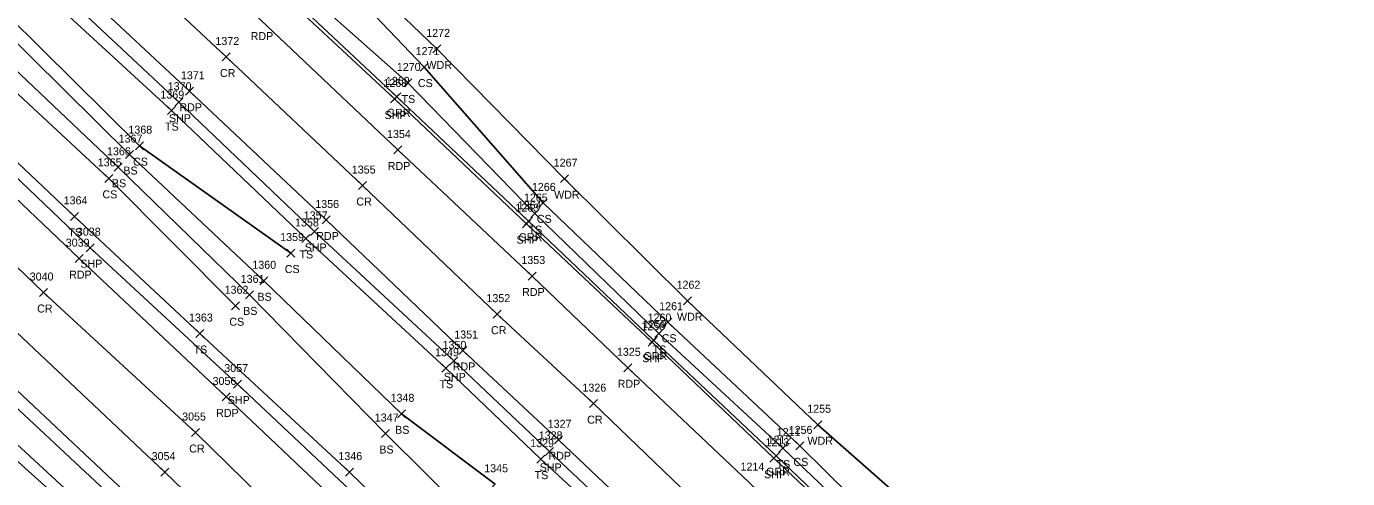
# Model space of a CAD drawing. Extents: x 1647574 to 1652703, y 212895 to 228670.
# Drawn here: x 1649589.7 to 1649920, y 226490.7 to 226603.8 of the extents above; entities that cross this region are included whole.
import ezdxf

# ---------------------------------------------------------------- set-up
doc = ezdxf.new("R2010")
doc.units = 0
for name, color, linetype in [('L_A', 7, 'Continuous'), ('L_I', 7, 'Continuous'), ('L_TIC', 7, 'Continuous'), ('LAWA', 7, 'Continuous'), ('LELB', 7, 'Continuous'), ('P_A', 7, 'Continuous'), ('P_I', 7, 'Continuous'), ('P_TIC', 7, 'Continuous'), ('PET', 7, 'Continuous'), ('PRC', 7, 'Continuous'), ('PSP', 7, 'Continuous'), ('R_A', 7, 'Continuous'), ('R_I', 7, 'Continuous'), ('R_TIC', 7, 'Continuous'), ('RGR', 7, 'Continuous')]:
    doc.layers.add(name, color=color, linetype=linetype)

msp = doc.modelspace()

# ---------------------------------------------------------------- linework, layer by layer
at = {"layer": 'L_TIC'}
for points in [[(1649691.31, 226597.17), (1649693.31, 226599.17)], [(1649693.31, 226597.17), (1649691.31, 226599.17)], [(1649688.09, 226592.62), (1649690.09, 226594.62)], [(1649690.09, 226592.62), (1649688.09, 226594.62)], [(1649684.05, 226588.65), (1649686.05, 226590.65)], [(1649686.05, 226588.65), (1649684.05, 226590.65)], [(1649624.91, 226581.74), (1649626.91, 226583.74)], [(1649626.91, 226581.74), (1649624.91, 226583.74)], [(1649614.46, 226570.75), (1649616.46, 226572.75)], [(1649616.46, 226570.75), (1649614.46, 226572.75)], [(1649616.9, 226572.97), (1649618.9, 226574.97)], [(1649618.9, 226572.97), (1649616.9, 226574.97)], [(1649611.61, 226567.57), (1649613.61, 226569.57)], [(1649613.61, 226567.57), (1649611.61, 226569.57)], [(1649609.24, 226564.8), (1649611.24, 226566.8)], [(1649611.24, 226564.8), (1649609.24, 226566.8)], [(1649723.22, 226564.72), (1649725.22, 226566.72)], [(1649725.22, 226564.72), (1649723.22, 226566.72)], [(1649717.83, 226558.66), (1649719.83, 226560.66)], [(1649719.83, 226558.66), (1649717.83, 226560.66)], [(1649600.72, 226555.3), (1649602.72, 226557.3)], [(1649602.72, 226555.3), (1649600.72, 226557.3)], [(1649715.78, 226555.99), (1649717.78, 226557.99)], [(1649717.78, 226555.99), (1649715.78, 226557.99)], [(1649658.53, 226549.77), (1649660.53, 226551.77)], [(1649660.53, 226549.77), (1649658.53, 226551.77)], [(1649654.81, 226546.12), (1649656.81, 226548.12)], [(1649656.81, 226546.12), (1649654.81, 226548.12)], [(1649647.98, 226539.18), (1649649.98, 226541.18)], [(1649649.98, 226539.18), (1649647.98, 226541.18)], [(1649644.41, 226535.66), (1649646.41, 226537.66)], [(1649646.41, 226535.66), (1649644.41, 226537.66)], [(1649753.94, 226534.2), (1649755.94, 226536.2)], [(1649755.94, 226534.2), (1649753.94, 226536.2)], [(1649640.96, 226532.94), (1649642.96, 226534.94)], [(1649642.96, 226532.94), (1649640.96, 226534.94)], [(1649749.04, 226528.83), (1649751.04, 226530.83)], [(1649751.04, 226528.83), (1649749.04, 226530.83)], [(1649632.05, 226525.99), (1649634.05, 226527.99)], [(1649634.05, 226525.99), (1649632.05, 226527.99)], [(1649746.79, 226525.99), (1649748.79, 226527.99)], [(1649748.79, 226525.99), (1649746.79, 226527.99)], [(1649693.54, 226517.32), (1649695.54, 226519.32)], [(1649695.54, 226517.32), (1649693.54, 226519.32)], [(1649682.4, 226505.92), (1649684.4, 226507.92)], [(1649684.4, 226505.92), (1649682.4, 226507.92)], [(1649678.45, 226500.99), (1649680.45, 226502.99)], [(1649680.45, 226500.99), (1649678.45, 226502.99)], [(1649786.56, 226503.18), (1649788.56, 226505.18)], [(1649788.56, 226503.18), (1649786.56, 226505.18)], [(1649781.98, 226497.9), (1649783.98, 226499.9)], [(1649783.98, 226497.9), (1649781.98, 226499.9)], [(1649717.31, 226494.58), (1649719.31, 226496.58)], [(1649719.31, 226494.58), (1649717.31, 226496.58)], [(1649777.8, 226497.35), (1649779.8, 226499.35)], [(1649779.8, 226497.35), (1649777.8, 226499.35)], [(1649669.41, 226491.35), (1649671.41, 226493.35)], [(1649671.41, 226491.35), (1649669.41, 226493.35)]]:
    msp.add_lwpolyline(points, dxfattribs=at)
at = {"layer": 'LAWA'}
msp.add_lwpolyline([(1650224.82, 226043.26), (1650200.57, 226071.14), (1650179.14, 226096.39), (1650156.93, 226122.13), (1650126.46, 226158.5), (1650102.32, 226186.03), (1650070.86, 226221.7), (1650047.25, 226248.26), (1650033.72, 226259.55), (1650015.55, 226280.28), (1649981.36, 226313.37), (1649950.59, 226346.36), (1649922.81, 226373.8), (1649891.44, 226407.34), (1649856.77, 226439.08), (1649829.63, 226467.03), (1649787.56, 226504.18), (1649754.94, 226535.2), (1649724.22, 226565.72), (1649692.31, 226598.17), (1649653.67, 226635.29), (1649620.52, 226666.86), (1649581.67, 226703.66)], dxfattribs=at)
at = {"layer": 'LELB'}
for points in [[(1649699.67, 226481.91), (1649679.45, 226501.99), (1649645.41, 226536.66), (1649612.61, 226568.57), (1649578.32, 226600.99), (1649543.98, 226632.95), (1649509.04, 226666.44), (1649473.07, 226698.81), (1649440.27, 226731.3), (1649435.72, 226737.04), (1649408.87, 226762.28), (1649371.65, 226797.42), (1649335.46, 226831.54), (1649323.17, 226842.84), (1649315.96, 226850.35), (1649312.9, 226852.88), (1649303.05, 226862.63), (1649272.9, 226885.04), (1649244.53, 226913.23), (1649219.14, 226937.73), (1649217.77, 226942.22), (1649215.75, 226944.46), (1649217.78, 226946.35), (1649219.53, 226943.85)], [(1650010.63, 226272.18), (1649976.36, 226308.87), (1649944.85, 226340.83), (1649916.6, 226368.96), (1649885.58, 226401.45), (1649851.41, 226433.71), (1649822.12, 226460.28), (1649782.98, 226498.9), (1649750.04, 226529.83), (1649718.83, 226559.66), (1649689.09, 226593.62), (1649652.01, 226632.5), (1649616.85, 226664.27), (1649578.69, 226701.52), (1649544.7, 226732.63), (1649511.82, 226765.51), (1649477.06, 226797.14), (1649442.21, 226831.27), (1649405.15, 226865.62), (1649378.95, 226891.41), (1649346.59, 226917.07), (1649311.19, 226946.22)], [(1649699.67, 226481.91), (1649706.82, 226489.3), (1649683.4, 226506.92), (1649648.98, 226540.18), (1649615.46, 226571.75), (1649582.54, 226604.31), (1649545.88, 226635.11), (1649514.99, 226670.75), (1649476.91, 226703.47), (1649443.87, 226735.13), (1649437.39, 226738.45), (1649410.25, 226763.49), (1649372.93, 226798.59), (1649336.35, 226832.76), (1649324.5, 226844.21), (1649317.41, 226851.47), (1649314.57, 226854.84), (1649305.82, 226864.42), (1649279.73, 226892.76), (1649248.17, 226918.18), (1649224.51, 226943.02), (1649219.53, 226943.85)], [(1650213.15, 226037.1), (1650185.87, 226070.33), (1650156.97, 226103.72), (1650126.82, 226139.03), (1650097.45, 226172.49), (1650065.12, 226208.19), (1650039.15, 226236.7), (1650005.62, 226272.51), (1649977.06, 226302.34), (1649946.85, 226333.69), (1649915.81, 226365.02), (1649884.88, 226395.87), (1649852.74, 226426.8), (1649817.4, 226461.44), (1649778.8, 226498.35), (1649747.79, 226526.99), (1649716.78, 226556.99), (1649685.05, 226589.65), (1649647.22, 226623.29), (1649611.68, 226660.43), (1649573.8, 226694.76)], [(1649655.81, 226547.12), (1649617.9, 226573.97), (1649585.1, 226606.47), (1649550.01, 226639.37), (1649514.99, 226670.75)], [(1649641.96, 226533.94), (1649610.24, 226565.8), (1649574.72, 226598.75), (1649541.82, 226631.16), (1649509.04, 226666.44)], [(1650145.31, 225996.12), (1650155.22, 226000.73), (1650160.97, 226007.39), (1650165.06, 226014.73), (1650162.63, 226023.17), (1650152.14, 226036.38), (1650125.52, 226068.74), (1650101.36, 226098.15), (1650073.79, 226131.47), (1650039.14, 226169.85), (1650006.52, 226208.67), (1649978.85, 226238.77), (1649944.11, 226276), (1649910.77, 226309.61), (1649879.19, 226341.22), (1649849.26, 226371.24), (1649815.2, 226404.44), (1649786.47, 226431.97), (1649749.39, 226466.79), (1649718.31, 226495.58), (1649694.54, 226518.32), (1649659.53, 226550.77), (1649625.91, 226582.74), (1649593.12, 226613.01)], [(1650145.31, 225996.12), (1650126.11, 226017.39), (1650101.66, 226047.08), (1650074.02, 226078.27), (1650048.35, 226107.52), (1650011.02, 226148.89), (1649978.29, 226184.76), (1649948.32, 226216.56), (1649918.31, 226248.62), (1649881.09, 226286.67), (1649854.51, 226315.1), (1649822.53, 226345.57), (1649790.94, 226377.4), (1649759.46, 226406.66), (1649722.98, 226440.72), (1649699.36, 226464.18), (1649670.41, 226492.35), (1649633.05, 226526.99), (1649601.72, 226556.3), (1649565.56, 226590.44)], [(1649576.43, 226518.4), (1649614.41, 226482.98), (1649642.41, 226455.9), (1649685.38, 226415.67), (1649721.92, 226380.74), (1649759.16, 226344.82), (1649794.41, 226310.27), (1649829.09, 226276.12), (1649866.9, 226238.21), (1649900.81, 226202.84), (1649937.1, 226163.93), (1649969.44, 226128.19), (1649998.01, 226097.17), (1650029.45, 226060.68), (1650045.36, 226034.05), (1650069.99, 226009.77), (1650092.51, 225984.63), (1650111.94, 225960.02)], [(1649572.06, 226513.32), (1649610.08, 226478.23), (1649638.08, 226450.58), (1649682.17, 226412.39), (1649718, 226377.59), (1649756, 226340.45), (1649789.26, 226306.39), (1649824.84, 226270.98), (1649865.01, 226237.13), (1649898.41, 226199.96), (1649935.32, 226162.62), (1649968.54, 226127.19), (1649995.98, 226095.51), (1650026.38, 226057.31)], [(1649570.19, 226510.51), (1649608.23, 226476.35), (1649636.57, 226449.06), (1649663.19, 226421.28), (1649670.48, 226414.78), (1649679.22, 226408.18), (1649715.79, 226375.57), (1649754.34, 226338.61), (1649788.1, 226305.21), (1649822.67, 226268.96), (1649860.5, 226231.77), (1649895.97, 226193.57), (1649929.13, 226157.26), (1649962.02, 226120.66), (1649988.9, 226089.08), (1650019.8, 226051.49), (1650041.89, 226022.86), (1650059.37, 225999.62), (1650079.66, 225974.03), (1650096.25, 225946.36)]]:
    msp.add_lwpolyline(points, dxfattribs=at)
at = {"layer": 'P_TIC'}
for points in [[(1649638.62, 226595.15), (1649640.62, 226597.15)], [(1649640.62, 226595.15), (1649638.62, 226597.15)], [(1649626.77, 226583.84), (1649628.77, 226585.84)], [(1649628.77, 226583.84), (1649626.77, 226585.84)], [(1649629.41, 226586.57), (1649631.41, 226588.57)], [(1649631.41, 226586.57), (1649629.41, 226588.57)], [(1649680.67, 226584.65), (1649682.67, 226586.65)], [(1649682.67, 226584.65), (1649680.67, 226586.65)], [(1649681.51, 226571.89), (1649683.51, 226573.89)], [(1649683.51, 226571.89), (1649681.51, 226573.89)], [(1649672.7, 226563), (1649674.7, 226565)], [(1649674.7, 226563), (1649672.7, 226565)], [(1649663.62, 226554.39), (1649665.62, 226556.39)], [(1649665.62, 226554.39), (1649663.62, 226556.39)], [(1649660.7, 226551.53), (1649662.7, 226553.53)], [(1649662.7, 226551.53), (1649660.7, 226553.53)], [(1649713.65, 226553.46), (1649715.65, 226555.46)], [(1649715.65, 226553.46), (1649713.65, 226555.46)], [(1649604.62, 226547.46), (1649606.62, 226549.46)], [(1649606.62, 226547.46), (1649604.62, 226549.46)], [(1649601.84, 226544.72), (1649603.84, 226546.72)], [(1649603.84, 226544.72), (1649601.84, 226546.72)], [(1649715.1, 226540.38), (1649717.1, 226542.38)], [(1649717.1, 226540.38), (1649715.1, 226542.38)], [(1649592.92, 226536.25), (1649594.92, 226538.25)], [(1649594.92, 226536.25), (1649592.92, 226538.25)], [(1649706.37, 226530.84), (1649708.37, 226532.84)], [(1649708.37, 226530.84), (1649706.37, 226532.84)], [(1649697.76, 226521.75), (1649699.76, 226523.75)], [(1649699.76, 226521.75), (1649697.76, 226523.75)], [(1649745.09, 226523.83), (1649747.09, 226525.83)], [(1649747.09, 226523.83), (1649745.09, 226525.83)], [(1649695.48, 226519.16), (1649697.48, 226521.16)], [(1649697.48, 226519.16), (1649695.48, 226521.16)], [(1649738.98, 226517.42), (1649740.98, 226519.42)], [(1649740.98, 226517.42), (1649738.98, 226519.42)], [(1649641.47, 226513.36), (1649643.47, 226515.36)], [(1649643.47, 226513.36), (1649641.47, 226515.36)], [(1649638.6, 226510.14), (1649640.6, 226512.14)], [(1649640.6, 226510.14), (1649638.6, 226512.14)], [(1649730.42, 226508.46), (1649732.42, 226510.46)], [(1649732.42, 226508.46), (1649730.42, 226510.46)], [(1649630.94, 226501.23), (1649632.94, 226503.23)], [(1649632.94, 226501.23), (1649630.94, 226503.23)], [(1649721.68, 226499.42), (1649723.68, 226501.42)], [(1649723.68, 226499.42), (1649721.68, 226501.42)], [(1649719.44, 226496.53), (1649721.44, 226498.53)], [(1649721.44, 226496.53), (1649719.44, 226498.53)], [(1649775.56, 226494.81), (1649777.56, 226496.81)], [(1649777.56, 226494.81), (1649775.56, 226496.81)], [(1649623.3, 226491.34), (1649625.3, 226493.34)], [(1649625.3, 226491.34), (1649623.3, 226493.34)]]:
    msp.add_lwpolyline(points, dxfattribs=at)
at = {"layer": 'PET'}
for points in [[(1650203.46, 226029.18), (1650176.21, 226061.89), (1650147.53, 226095.79), (1650117.29, 226130.73), (1650087.4, 226164.52), (1650055.9, 226199.34), (1650029.44, 226228.14), (1649996.95, 226263.47), (1649968.15, 226293.72), (1649938.19, 226324.52), (1649906.65, 226356.13), (1649876.52, 226386.27), (1649843.75, 226418.81), (1649809.66, 226451.94), (1649770.32, 226489.71), (1649739.98, 226518.42), (1649716.1, 226541.38), (1649682.51, 226572.89), (1649648.23, 226605.38), (1649615.14, 226636.4), (1649578.52, 226671.42)], [(1650180.12, 226018.51), (1650160.2, 226042.42), (1650132.53, 226074.87), (1650108.24, 226103.36), (1650079.8, 226135.84), (1650045.18, 226174.49), (1650010.43, 226212.6), (1649983.21, 226241.97), (1649947.38, 226279.71), (1649914.98, 226313), (1649883.03, 226345), (1649852.9, 226374.89), (1649819.24, 226408.27), (1649790.46, 226435.99), (1649753.36, 226471.35), (1649722.68, 226500.42), (1649698.76, 226522.75), (1649664.62, 226555.39), (1649630.41, 226587.57), (1649598.45, 226617.55), (1649561.34, 226652.9)], [(1649568.76, 226578.15), (1649602.84, 226545.72), (1649639.6, 226511.14), (1649669.58, 226482.71), (1649710.56, 226443.02), (1649749.16, 226406.1), (1649783.82, 226372.91), (1649821.53, 226335.91), (1649854.36, 226303.39), (1649893.84, 226262.84), (1649926.53, 226228.81), (1649964.59, 226188.34), (1649995.88, 226154.08), (1650026.58, 226120.39), (1650056.63, 226086.43), (1650078.17, 226061.47), (1650102.87, 226032.97), (1650121.07, 226011.5), (1650140.46, 225987.82)], [(1649585.69, 226528.77), (1649624.3, 226492.34), (1649652.1, 226465.47), (1649694.18, 226424.93), (1649731.2, 226389.82), (1649767.06, 226355.29), (1649804.34, 226318.78), (1649837.23, 226285.73), (1649875.09, 226247.37), (1649909.48, 226211.77), (1649946.37, 226172.47), (1649978.25, 226137.54), (1650007.65, 226104.95), (1650038.73, 226069.71), (1650059.42, 226046.29), (1650084.31, 226017.14), (1650102.55, 225995.44), (1650123.3, 225970.1)]]:
    msp.add_lwpolyline(points, dxfattribs=at)
at = {"layer": 'PRC'}
for points in [[(1650190.29, 226025.07), (1650169.4, 226050.68), (1650141.73, 226083.3), (1650117.9, 226111.09), (1650088.92, 226144.57), (1650053.94, 226182.93), (1650019.72, 226220.45), (1649992.16, 226250.42), (1649956.56, 226288.56), (1649923.88, 226321.79), (1649891.54, 226354.39), (1649861.68, 226384.4), (1649827.7, 226416.9), (1649798.54, 226445.37), (1649761.96, 226480.16), (1649731.42, 226509.46), (1649707.37, 226531.84), (1649673.7, 226564), (1649639.62, 226596.15), (1649606.75, 226626.95), (1649570.25, 226661.64)], [(1649559.91, 226569.96), (1649593.92, 226537.25), (1649631.94, 226502.23), (1649660.46, 226474.34), (1649702.15, 226434.36), (1649740.4, 226397.48), (1649775.04, 226364.12), (1649813.32, 226327.22), (1649846.03, 226294.55), (1649884.93, 226255.04), (1649918.06, 226220.06), (1649955.14, 226180.9), (1649987.04, 226146.06), (1650016.78, 226113.16), (1650047.62, 226077.89), (1650069.26, 226053.4), (1650093.06, 226025.47), (1650111.86, 226003.86), (1650131.21, 225979.86)]]:
    msp.add_lwpolyline(points, dxfattribs=at)
at = {"layer": 'PSP'}
for points in [[(1650209.98, 226034.8), (1650182.89, 226067.68), (1650153.83, 226101.81), (1650124.05, 226136.25), (1650094.35, 226170.32), (1650062.83, 226205.52), (1650036.19, 226234.57), (1650003.11, 226270.29), (1649975.25, 226299.75), (1649944.68, 226331.46), (1649913.77, 226362.55), (1649883.23, 226393.29), (1649850.54, 226425.12), (1649815.25, 226459.11), (1649776.56, 226495.81), (1649746.09, 226524.83), (1649714.65, 226554.46), (1649681.67, 226585.65), (1649644.69, 226620.23), (1649606.95, 226655.87), (1649570.92, 226690.01)], [(1650176.78, 226014.91), (1650174.69, 226018.89), (1650157.03, 226040.39), (1650129.97, 226072.67), (1650105.28, 226101.15), (1650076.93, 226133.75), (1650041.79, 226172.07), (1650008.03, 226209.64), (1649980.35, 226240.01), (1649944.97, 226277.48), (1649912.15, 226310.56), (1649880.37, 226342.42), (1649850.35, 226372.48), (1649816.61, 226405.58), (1649787.78, 226433.35), (1649750.91, 226468.71), (1649720.44, 226497.53), (1649696.48, 226520.16), (1649661.7, 226552.53), (1649627.77, 226584.84), (1649595.64, 226615.02), (1649558.33, 226650.15)], [(1649571.18, 226581.28), (1649605.62, 226548.46), (1649642.47, 226514.36), (1649673.51, 226485.11), (1649713.05, 226446.56), (1649753.13, 226408.58), (1649786.75, 226376.31), (1649825.02, 226339.17), (1649858.01, 226306.81), (1649897.5, 226266.11), (1649930.08, 226232.3), (1649968.22, 226191.53), (1649999.65, 226157.4), (1650029.99, 226123.79), (1650060.42, 226089.05), (1650081.82, 226064.3), (1650106.87, 226035.38), (1650124.34, 226014.45), (1650143.68, 225990.93)], [(1649578.75, 226520.79), (1649616.88, 226484.95), (1649644.67, 226458.4), (1649687.66, 226417.66), (1649724.18, 226382.77), (1649761.14, 226347.64), (1649797.11, 226312.71), (1649831.3, 226278.59), (1649868.9, 226240.31), (1649902.65, 226204.83), (1649939.09, 226165.73), (1649971.52, 226130.61), (1650000.21, 226098.9), (1650032.08, 226063.05), (1650053.34, 226038.39), (1650075.13, 226014.23), (1650096.57, 225988.88), (1650117.58, 225964.05)]]:
    msp.add_lwpolyline(points, dxfattribs=at)
at = {"layer": 'R_TIC'}
for points in [[(1649681.27, 226585.18), (1649683.27, 226587.18)], [(1649683.27, 226585.18), (1649681.27, 226587.18)], [(1649714.22, 226554.07), (1649716.22, 226556.07)], [(1649716.22, 226554.07), (1649714.22, 226556.07)], [(1649745.45, 226524.34), (1649747.45, 226526.34)], [(1649747.45, 226524.34), (1649745.45, 226526.34)], [(1649776.08, 226495.44), (1649778.08, 226497.44)], [(1649778.08, 226495.44), (1649776.08, 226497.44)]]:
    msp.add_lwpolyline(points, dxfattribs=at)
at = {"layer": 'RGR'}
msp.add_lwpolyline([(1650210.88, 226035.34), (1650183.47, 226068.36), (1650154.6, 226102.18), (1650124.72, 226137.1), (1650095.1, 226170.93), (1650063.42, 226206.14), (1650036.95, 226235.01), (1650003.69, 226270.69), (1649975.87, 226300.38), (1649945.2, 226332.04), (1649914.34, 226363.19), (1649883.95, 226393.7), (1649851.2, 226425.71), (1649815.73, 226459.46), (1649777.08, 226496.44), (1649746.45, 226525.34), (1649715.22, 226555.07), (1649682.27, 226586.18), (1649645.22, 226621.05), (1649607.54, 226656.38), (1649571.29, 226690.65)], dxfattribs=at)

# ---------------------------------------------------------------- texts
at = {"layer": 'L_A'}
for s, p in [('WDR', (1649689.68, 226593.17)), ('CS', (1649687.53, 226588.62)), ('TS', (1649683.46, 226584.65)), ('TS', (1649624.32, 226577.74)), ('CS', (1649616.34, 226568.97)), ('BS', (1649611.05, 226563.57)), ('BS', (1649613.9, 226566.75)), ('CS', (1649608.68, 226560.8)), ('WDR', (1649721.59, 226560.72)), ('CS', (1649717.27, 226554.66)), ('TS', (1649600.13, 226551.3)), ('TS', (1649715.19, 226551.99)), ('TS', (1649657.93, 226545.77)), ('CS', (1649654.25, 226542.12)), ('BS', (1649647.42, 226535.18)), ('BS', (1649643.85, 226531.66)), ('CS', (1649640.4, 226528.94)), ('WDR', (1649752.3, 226530.2)), ('CS', (1649748.48, 226524.83)), ('TS', (1649631.46, 226521.99)), ('TS', (1649746.2, 226521.99)), ('TS', (1649692.95, 226513.32)), ('BS', (1649681.84, 226501.92)), ('WDR', (1649784.92, 226499.18)), ('BS', (1649677.89, 226496.99)), ('TS', (1649777.21, 226493.35)), ('CS', (1649781.42, 226493.9)), ('TS', (1649716.72, 226490.58))]:
    msp.add_text(s, height=2, dxfattribs=at).set_placement(p)
at = {"layer": 'L_I'}
for s, p in [('1272', (1649689.62, 226601.17)), ('1271', (1649686.96, 226596.62)), ('1270', (1649682.27, 226592.65)), ('1369', (1649623.16, 226585.74)), ('1368', (1649615.16, 226576.97)), ('1367', (1649612.72, 226574.75)), ('1366', (1649609.81, 226571.57)), ('1365', (1649607.5, 226568.8)), ('1267', (1649721.48, 226568.72)), ('1266', (1649716.03, 226562.66)), ('1364', (1649598.98, 226559.3)), ('1265', (1649714.04, 226559.99)), ('1358', (1649656.83, 226553.77)), ('1359', (1649653.11, 226550.12)), ('1360', (1649646.15, 226543.18)), ('1361', (1649643.24, 226539.66)), ('1262', (1649752.2, 226538.2)), ('1362', (1649639.22, 226536.94)), ('1261', (1649747.86, 226532.83)), ('1363', (1649630.31, 226529.99)), ('1260', (1649744.96, 226529.99)), ('1349', (1649691.84, 226521.32)), ('1348', (1649680.7, 226509.92)), ('1347', (1649676.76, 226504.99)), ('1255', (1649784.87, 226507.18)), ('1211', (1649777.24, 226501.35)), ('1256', (1649780.23, 226501.9)), ('1329', (1649715.61, 226498.58)), ('1346', (1649667.66, 226495.35)), ('1345', (1649704.12, 226492.3))]:
    msp.add_text(s, height=2, dxfattribs=at).set_placement(p)
at = {"layer": 'P_A'}
for s, p in [('RDP', (1649645.72, 226600.38)), ('CR', (1649638.05, 226591.15)), ('RDP', (1649627.9, 226582.57)), ('SHP', (1649679.2, 226580.65)), ('SHP', (1649625.3, 226579.84)), ('RDP', (1649679.99, 226567.89)), ('CR', (1649672.13, 226559)), ('RDP', (1649662.11, 226550.39)), ('SHP', (1649659.24, 226547.53)), ('SHP', (1649712.19, 226549.46)), ('RDP', (1649600.33, 226540.72)), ('SHP', (1649603.16, 226543.46)), ('RDP', (1649713.59, 226536.38)), ('CR', (1649592.35, 226532.25)), ('CR', (1649705.8, 226526.84)), ('RDP', (1649696.24, 226517.75)), ('SHP', (1649743.63, 226519.83)), ('SHP', (1649694.01, 226515.16)), ('RDP', (1649737.47, 226513.42)), ('SHP', (1649640.01, 226509.36)), ('RDP', (1649637.09, 226506.14)), ('CR', (1649729.85, 226504.46)), ('CR', (1649630.37, 226497.23)), ('RDP', (1649720.17, 226495.42)), ('SHP', (1649717.97, 226492.53)), ('SHP', (1649774.09, 226490.81))]:
    msp.add_text(s, height=2, dxfattribs=at).set_placement(p)
at = {"layer": 'P_I'}
for s, p in [('1372', (1649636.92, 226599.15)), ('1371', (1649628.28, 226590.57)), ('1370', (1649624.99, 226587.84)), ('1268', (1649678.93, 226588.65)), ('1354', (1649679.81, 226575.89)), ('1355', (1649671.01, 226567)), ('1356', (1649661.88, 226558.39)), ('1263', (1649711.91, 226557.46)), ('1357', (1649659.01, 226555.53)), ('3038', (1649602.28, 226551.46)), ('3039', (1649599.5, 226548.72)), ('1353', (1649713.41, 226544.38)), ('3040', (1649590.49, 226540.25)), ('1352', (1649704.67, 226534.84)), ('1258', (1649743.4, 226527.83)), ('1351', (1649696.63, 226525.75)), ('1350', (1649693.7, 226523.16)), ('1325', (1649737.29, 226521.42)), ('3057', (1649639.13, 226517.36)), ('3056', (1649636.21, 226514.14)), ('1326', (1649728.67, 226512.46)), ('3055', (1649628.6, 226505.23)), ('1327', (1649719.99, 226503.42)), ('1328', (1649717.74, 226500.53)), ('1213', (1649774.43, 226498.81)), ('3054', (1649620.97, 226495.34)), ('1214', (1649768.19, 226492.71))]:
    msp.add_text(s, height=2, dxfattribs=at).set_placement(p)
at = {"layer": 'R_A'}
for p in [(1649679.76, 226581.18), (1649712.71, 226550.07), (1649743.94, 226520.34), (1649774.57, 226491.44)]:
    msp.add_text('GRR', height=2, dxfattribs=at).set_placement(p)
at = {"layer": 'R_I'}
for s, p in [('1269', (1649679.52, 226589.18)), ('1264', (1649712.48, 226558.07)), ('1259', (1649743.75, 226528.34)), ('1212', (1649774.95, 226499.44))]:
    msp.add_text(s, height=2, dxfattribs=at).set_placement(p)

doc.saveas('drawing.dxf')
